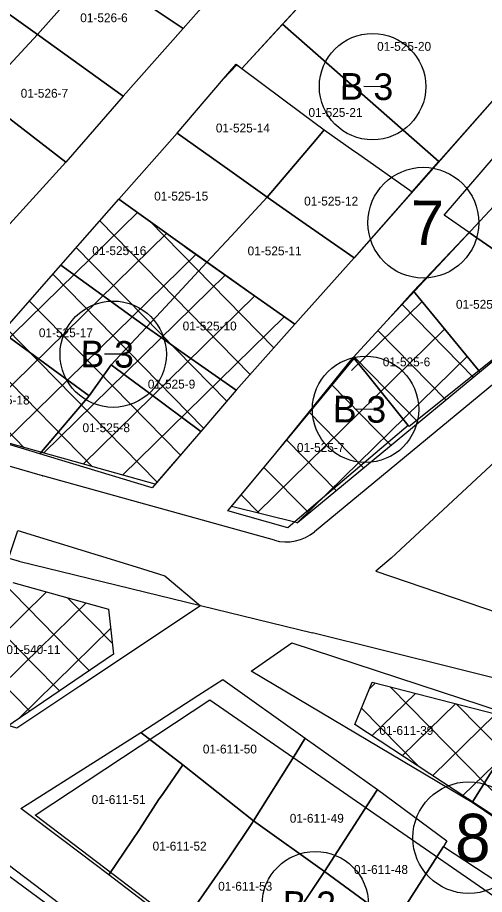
# Model space of a CAD drawing. Extents: x 413946 to 415528, y 4453939 to 4454944.
# Drawn here: x 415269.2 to 415321.9, y 4454344.2 to 4454443.2 of the extents above; entities that cross this region are included whole.
import ezdxf

# ---------------------------------------------------------------- set-up
doc = ezdxf.new("R2010")
doc.units = 0
for name, color, linetype in [('0_KADASTRO', 7, 'Continuous'), ('Level 27', 7, 'Continuous'), ('Level 28', 7, 'Continuous'), ('Level 29', 7, 'Continuous'), ('Level 32', 7, 'Continuous'), ('Level 34', 7, 'Continuous'), ('Level 57', 7, 'Continuous'), ('Level 58', 7, 'Continuous'), ('Level 62', 7, 'Continuous')]:
    doc.layers.add(name, color=color, linetype=linetype)

msp = doc.modelspace()

# ---------------------------------------------------------------- linework, layer by layer
at = {"layer": '0_KADASTRO'}
for p, q in [((415302.032, 4454445.623), (415299.101, 4454442.427)), ((415316.733, 4454426.917), (415333.88, 4454446.41)), ((415299.101, 4454442.427), (415294.498, 4454437.407)), ((415299.101, 4454442.427), (415316.733, 4454426.917)), ((415316.733, 4454426.917), (415299.101, 4454442.427)), ((415294.498, 4454437.407), (415301.31, 4454432.33)), ((415366.073, 4454432.984), (415311.34, 4454382.15)), ((415301.31, 4454432.33), (415303.797, 4454430.482)), ((415311.34, 4454382.15), (415309.615, 4454380.681))]:
    msp.add_line(p, q, dxfattribs=at)
for points in [[(415261.53, 4454448.35), (415268.31, 4454455.75), (415277.97, 4454448.59), (415271.45, 4454441.25)], [(415277.97, 4454448.59), (415284.17, 4454455.45), (415293.06, 4454447.82), (415287.9, 4454441.92)], [(415271.45, 4454441.25), (415277.97, 4454448.59), (415287.9, 4454441.92), (415281.11, 4454434.3)], [(415254.93, 4454441.05), (415261.53, 4454448.35), (415271.45, 4454441.25), (415264.97, 4454434.28)], [(415317.335, 4454420.852), (415324.527, 4454429.224), (415338.863, 4454445.911), (415340.02, 4454444.97), (415350.09, 4454436.8), (415355.158, 4454432.663), (415349.116, 4454424.694), (415342.154, 4454419.915), (415341.308, 4454419.335), (415330.359, 4454411.821), (415328, 4454413.45), (415325.63, 4454415.09), (415320.15, 4454418.9)], [(415264.97, 4454434.28), (415271.45, 4454441.25), (415281.11, 4454434.3), (415274.64, 4454426.85)], [(415287.22, 4454430.12), (415292.45, 4454436.24), (415293.85, 4454437.89), (415294.498, 4454437.407), (415301.31, 4454432.33), (415303.797, 4454430.482), (415302.89, 4454429.41), (415297.36, 4454422.87), (415293.13, 4454425.89)], [(415258.31, 4454426.82), (415264.97, 4454434.28), (415274.64, 4454426.85), (415267.96, 4454419.45)], [(415280.63, 4454422.65), (415287.22, 4454430.12), (415293.13, 4454425.89), (415297.36, 4454422.87), (415293.28, 4454418.47), (415290.55, 4454415.55), (415288.27, 4454417.18), (415288.031, 4454417.351)], [(415297.36, 4454422.87), (415302.89, 4454429.41), (415303.797, 4454430.482), (415303.8, 4454430.48), (415307.15, 4454428.12), (415307.437, 4454427.918), (415313.73, 4454423.5), (415307.16, 4454416.03), (415300.88, 4454420.41)], [(415290.55, 4454415.55), (415293.28, 4454418.47), (415297.36, 4454422.87), (415300.88, 4454420.41), (415307.16, 4454416.03), (415300.48, 4454408.55), (415294.92, 4454412.47), (415292.222, 4454414.372)], [(415274.07, 4454415.22), (415280.63, 4454422.65), (415288.031, 4454417.351), (415288.27, 4454417.18), (415290.55, 4454415.55), (415285.9, 4454410.51), (415283.75, 4454408.21)], [(415313.88, 4454412.26), (415320.15, 4454418.9), (415325.63, 4454415.09), (415328, 4454413.45), (415330.359, 4454411.821), (415331.16, 4454411.26), (415321.25, 4454403.28), (415321.16, 4454403.39)], [(415267.45, 4454407.66), (415274.07, 4454415.22), (415283.75, 4454408.21), (415280.79, 4454405.04), (415279.76, 4454403.95), (415277.28, 4454400.45), (415274.74, 4454402.31)], [(415283.75, 4454408.21), (415285.9, 4454410.51), (415290.55, 4454415.55), (415292.222, 4454414.372), (415294.92, 4454412.47), (415300.48, 4454408.55), (415293.87, 4454401.09), (415287.63, 4454405.48), (415285.35, 4454407.09)], [(415307.07, 4454404.78), (415310.89, 4454408.98), (415313.88, 4454412.26), (415321.16, 4454403.39), (415321.25, 4454403.28), (415313.38, 4454396.99), (415313.28, 4454397.1), (415308.55, 4454402.98), (415307.19, 4454404.68)], [(415279.76, 4454403.95), (415280.79, 4454405.04), (415283.75, 4454408.21), (415285.35, 4454407.09), (415287.63, 4454405.48), (415293.87, 4454401.09), (415289.86, 4454396.45), (415283.82, 4454400.94), (415281.52, 4454402.64)], [(415258.83, 4454397.82), (415267.45, 4454407.66), (415274.74, 4454402.31), (415277.28, 4454400.45), (415274.26, 4454396.92), (415271.72, 4454393.93), (415268.37, 4454394.95)], [(415292.93, 4454387.5), (415298.35, 4454394.01), (415307.19, 4454404.68), (415308.55, 4454402.98), (415313.28, 4454397.1), (415302.86, 4454388.29), (415299.68, 4454385.58)], [(415271.72, 4454393.93), (415274.26, 4454396.92), (415277.28, 4454400.45), (415279.76, 4454403.95), (415281.52, 4454402.64), (415283.82, 4454400.94), (415289.86, 4454396.45), (415284.38, 4454390.08), (415273.83, 4454393.29)], [(415262.5, 4454364.97), (415267.23, 4454379.26), (415269.22, 4454385.27), (415282.582, 4454381.146), (415285.81, 4454380.15), (415289.82, 4454376.75), (415276.237, 4454367.69), (415269.13, 4454362.95)], [(415295.555, 4454369.37), (415300.13, 4454372.6), (415326.38, 4454363.96), (415320.5, 4454354.58)], [(415283.11, 4454362.48), (415289.53, 4454366.63), (415292.342, 4454368.448), (415301.659, 4454361.808), (415300.6, 4454360.11), (415295.818, 4454352.483), (415287.86, 4454358.8)], [(415320.5, 4454354.58), (415326.38, 4454363.96), (415332.434, 4454361.983), (415336.408, 4454360.685), (415335.327, 4454359.002), (415335.23, 4454358.85), (415329.384, 4454349.746), (415329.2, 4454349.46), (415328.843, 4454348.904)], [(415269.577, 4454353.893), (415270.99, 4454354.79), (415283.11, 4454362.48), (415287.86, 4454358.8), (415285.63, 4454355.59), (415285.11, 4454354.88), (415282.96, 4454351.53), (415279.49, 4454346.4), (415274.41, 4454350.24)], [(415295.818, 4454352.483), (415300.6, 4454360.11), (415301.659, 4454361.808), (415309.793, 4454356.011), (415309.11, 4454354.95), (415303.84, 4454346.76)], [(415279.49, 4454346.4), (415282.96, 4454351.53), (415285.11, 4454354.88), (415285.63, 4454355.59), (415287.86, 4454358.8), (415295.818, 4454352.483), (415295.642, 4454352.203), (415292.951, 4454348.21), (415287.47, 4454340.29)], [(415303.84, 4454346.76), (415309.11, 4454354.95), (415309.793, 4454356.011), (415317.644, 4454350.233), (415317.24, 4454349.6), (415311.832, 4454341.132), (415311.723, 4454340.968)], [(415287.47, 4454340.29), (415292.951, 4454348.21), (415295.642, 4454352.203), (415295.818, 4454352.483), (415303.84, 4454346.76), (415301.11, 4454342.71), (415299.81, 4454340.66), (415295.54, 4454334.36)], [(415311.723, 4454340.968), (415311.832, 4454341.132), (415317.24, 4454349.6), (415325.66, 4454344.07), (415319.586, 4454334.814)], [(415259.73, 4454335.58), (415262.46, 4454339.35), (415263.86, 4454341.48), (415265.14, 4454343.31), (415268.14, 4454347.57), (415275.96, 4454341.63), (415271.42, 4454334.96), (415270.31, 4454333.38), (415267.64, 4454329.34), (415265.69, 4454330.906), (415263.32, 4454332.81)], [(415295.54, 4454334.36), (415299.81, 4454340.66), (415301.11, 4454342.71), (415303.84, 4454346.76), (415311.723, 4454340.968), (415309.242, 4454337.05), (415308.171, 4454335.358), (415303.45, 4454328.46)]]:
    msp.add_lwpolyline(points, close=True, dxfattribs=at)
for points in [[(415303.797, 4454430.482), (415307.15, 4454428.12), (415307.437, 4454427.918), (415313.73, 4454423.5), (415316.733, 4454426.917)], [(415309.615, 4454380.681), (415325.168, 4454375.352), (415337.29, 4454371.2), (415365.59, 4454359.91), (415395.51, 4454353.22), (415454.59, 4454336.95), (415483.71, 4454327.37), (415486.352, 4454325.548)]]:
    msp.add_lwpolyline(points, dxfattribs=at)
at = {"layer": 'Level 27'}
for p, q in [((415336.625, 4454344.047), (415307.251, 4454363.349)), ((415313.299, 4454321.085), (415271.195, 4454353.137))]:
    msp.add_line(p, q, dxfattribs=at)
for points in [[(415310.574, 4454466.789), (415305.2, 4454460.96), (415299.8, 4454455.11), (415293.06, 4454447.82), (415287.9, 4454441.92), (415281.11, 4454434.3), (415274.64, 4454426.85), (415267.96, 4454419.45), (415261.25, 4454411.96), (415254.68, 4454404.53), (415250.364, 4454399.64)], [(415261.285, 4454400.622), (415267.45, 4454407.66), (415274.07, 4454415.22), (415280.63, 4454422.65), (415287.22, 4454430.12), (415292.45, 4454436.24), (415293.926, 4454437.825), (415294.498, 4454437.407), (415302.032, 4454445.623), (415316.534, 4454461.44)], [(415333.882, 4454446.412), (415307.16, 4454416.03), (415300.48, 4454408.55), (415293.87, 4454401.09), (415289.86, 4454396.45), (415284.734, 4454390.491)], [(415293.332, 4454387.982), (415298.35, 4454394.01), (415307.07, 4454404.78), (415310.89, 4454408.98), (415341.276, 4454441.532)], [(415345.55, 4454423.109), (415300.796, 4454386.141)], [(415264.984, 4454348.669), (415274.805, 4454341.419), (415313.615, 4454312.821), (415331.254, 4454309.711), (415373.854, 4454288.964), (415353.123, 4454256.024)]]:
    msp.add_lwpolyline(points, dxfattribs=at)
at = {"layer": 'Level 28'}
for p, q in [((415280.031, 4454371.288), (415278.27, 4454370.094)), ((415278.268, 4454370.094), (415257.121, 4454355.751)), ((415278.269, 4454370.094), (415278.268, 4454370.094)), ((415278.269, 4454370.094), (415278.268, 4454370.094)), ((415278.27, 4454370.094), (415278.269, 4454370.094))]:
    msp.add_line(p, q, dxfattribs=at)
for points in [[(415284.734, 4454390.491), (415263.836, 4454396.314), (415261.285, 4454400.622)], [(415300.796, 4454386.141), (415293.332, 4454387.982)], [(415268.668, 4454379.396), (415279.451, 4454376.391)], [(415271.195, 4454353.137), (415290.879, 4454366.166), (415303.916, 4454357.149)]]:
    msp.add_lwpolyline(points, dxfattribs=at)
at = {"layer": 'Level 29'}
for points in [[(415279.451, 4454376.391), (415280.031, 4454371.288)], [(415307.251, 4454363.349), (415309.19, 4454368.129), (415333.308, 4454361.932), (415343.508, 4454355.088)], [(415303.916, 4454357.149), (415330.56, 4454338.719), (415330.845, 4454335.266)]]:
    msp.add_lwpolyline(points, dxfattribs=at)
at = {"layer": 'Level 32'}
for p, q in [((415310.249, 4454435.356), (415308.249, 4454435.376)), ((415280.988, 4454405.152), (415278.988, 4454405.173)), ((415309.454, 4454398.931), (415307.454, 4454398.952))]:
    msp.add_line(p, q, dxfattribs=at)
for centre in [(415309.249, 4454435.366), (415279.988, 4454405.162), (415308.454, 4454398.941), (415302.791, 4454343.03)]:
    msp.add_circle(centre, 6, dxfattribs=at)
at = {"layer": 'Level 34'}
for p, q in [((415261.458, 4454400.33), (415282.722, 4454421.164)), ((415295.453, 4454402.876), (415278.473, 4454420.207)), ((415298.112, 4454405.877), (415284.08, 4454420.2)), ((415263.556, 4454396.786), (415286.036, 4454418.81)), ((415292.807, 4454399.86), (415275.818, 4454417.2)), ((415267.693, 4454395.239), (415289.349, 4454416.457)), ((415272.143, 4454393.999), (415292.662, 4454414.103)), ((415290.183, 4454396.824), (415273.168, 4454414.19)), ((415287.564, 4454393.781), (415270.525, 4454411.172)), ((415276.593, 4454392.759), (415295.976, 4454411.75)), ((415306.884, 4454403.314), (415314.832, 4454411.101)), ((415320.65, 4454402.541), (415312.574, 4454410.784)), ((415281.043, 4454391.519), (415299.289, 4454409.396)), ((415284.946, 4454390.737), (415267.882, 4454408.154)), ((415296.223, 4454387.269), (415317.38, 4454407.996)), ((415317.555, 4454399.984), (415309.856, 4454407.843)), ((415277.655, 4454392.464), (415265.239, 4454405.136)), ((415300.721, 4454386.079), (415319.927, 4454404.892)), ((415314.457, 4454397.426), (415307.16, 4454404.879)), ((415269.952, 4454394.61), (415262.596, 4454402.118)), ((415311.364, 4454394.87), (415304.621, 4454401.755)), ((415308.269, 4454392.315), (415302.087, 4454398.625)), ((415305.175, 4454389.758), (415299.553, 4454395.496)), ((415302.08, 4454387.201), (415296.999, 4454392.387)), ((415296.474, 4454387.207), (415294.427, 4454389.297)), ((415270.977, 4454370.176), (415259.276, 4454382.118)), ((415276.639, 4454370.112), (415267.096, 4454379.851)), ((415264.228, 4454370.251), (415272.478, 4454378.334)), ((415279.893, 4454372.507), (415274.823, 4454377.681)), ((415269.879, 4454370.188), (415276.928, 4454377.094)), ((415275.529, 4454370.124), (415279.699, 4454374.21)), ((415255.59, 4454356.189), (415269.879, 4454370.188)), ((415270.572, 4454364.873), (415265.314, 4454370.239)), ((415269.264, 4454363.986), (415275.529, 4454370.124)), ((415270.977, 4454370.176), (415270.977, 4454370.176)), ((415270.977, 4454370.176), (415270.977, 4454370.176)), ((415270.977, 4454370.176), (415270.977, 4454370.176)), ((415273.936, 4454367.155), (415270.977, 4454370.176)), ((415275.529, 4454370.124), (415275.529, 4454370.124)), ((415275.529, 4454370.124), (415275.529, 4454370.124)), ((415277.301, 4454369.436), (415276.639, 4454370.112)), ((415308.891, 4454367.392), (415309.549, 4454368.037)), ((415330.176, 4454348.285), (415311.253, 4454367.599)), ((415309.184, 4454362.079), (415314.077, 4454366.873)), ((415312.605, 4454359.831), (415318.606, 4454365.71)), ((415337.91, 4454346.108), (415318.736, 4454365.676)), ((415314.454, 4454358.616), (415308.002, 4454365.201)), ((415316.026, 4454357.583), (415323.134, 4454364.546)), ((415319.447, 4454355.335), (415327.662, 4454363.383))]:
    msp.add_line(p, q, dxfattribs=at)
at = {"layer": 'Level 57'}
for p, q in [((415280.63, 4454422.65), (415300.48, 4454408.55)), ((415313.914, 4454412.219), (415321.369, 4454403.135))]:
    msp.add_line(p, q, dxfattribs=at)
at = {"layer": 'Level 58'}
for centre, radius in [((415314.972, 4454420.004), 6.25), ((415320.092, 4454350.594), 6.3)]:
    msp.add_circle(centre, radius, dxfattribs=at)
at = {"layer": 'Level 62'}
for points in [[(415350.019, 4454424.206), (415302.694, 4454385.115)], [(415272.017, 4454391.439), (415205.951, 4454410.588)], [(415196.73, 4454402.847), (415269.364, 4454381.797)], [(415298.168, 4454384.153), (415272.067, 4454391.425)], [(415269.339, 4454381.804), (415302.49, 4454373.704)], [(415318.779, 4454369.638), (415302.49, 4454373.704)], [(415318.78, 4454369.638), (415318.779, 4454369.638)], [(415318.782, 4454369.638), (415318.781, 4454369.638)], [(415406.476, 4454347.755), (415318.782, 4454369.638)]]:
    msp.add_lwpolyline(points, dxfattribs=at)
for centre, start, end in [((415273.409, 4454396.242), 253.83563, 254.43059), ((415299.51, 4454388.97), 254.43219, 309.55705)]:
    msp.add_arc(centre, 5, start, end, dxfattribs=at)

# ---------------------------------------------------------------- texts
at = {"layer": '0_KADASTRO'}
for s, p in [('01-526-6', (415276.268, 4454442.638)), ('01-525-20', (415309.758, 4454439.407)), ('01-526-7', (415269.552, 4454434.113)), ('01-525-21', (415302.021, 4454431.949)), ('01-525-14', (415291.568, 4454430.192)), ('01-525-15', (415284.611, 4454422.508)), ('01-525-12', (415301.528, 4454421.943)), ('01-525-16', (415277.627, 4454416.347)), ('01-525-11', (415295.152, 4454416.318)), ('01-525-5', (415318.657, 4454410.292)), ('01-525-17', (415271.602, 4454407.084)), ('01-525-10', (415287.823, 4454407.845)), ('01-525-6', (415310.406, 4454403.792)), ('01-525-9', (415283.895, 4454401.287)), ('01-525-18', (415264.462, 4454399.485)), ('01-525-8', (415276.525, 4454396.363)), ('01-525-7', (415300.718, 4454394.136)), ('01-540-11', (415267.938, 4454371.32)), ('01-611-39', (415310.014, 4454362.196)), ('01-611-50', (415290.102, 4454360.096)), ('01-611-51', (415277.557, 4454354.391)), ('01-611-49', (415299.907, 4454352.279)), ('01-611-52', (415284.433, 4454349.141)), ('01-611-48', (415307.149, 4454346.501)), ('01-611-53', (415291.831, 4454344.606))]:
    msp.add_text(s, height=1, dxfattribs=at).set_placement(p)
at = {"layer": 'Level 32'}
for p in [(415305.55, 4454433.904), (415276.289, 4454403.7), (415304.755, 4454397.479), (415299.091, 4454341.567)]:
    msp.add_text('B 3', height=3, rotation=359.4141, dxfattribs=at).set_placement(p)
at = {"layer": 'Level 58'}
for s, height, p in [('7', 5, (415313.529, 4454417.519)), ('8', 5.4, (415318.534, 4454347.91))]:
    msp.add_text(s, height=height, rotation=359.4141, dxfattribs=at).set_placement(p)

doc.saveas('drawing.dxf')
